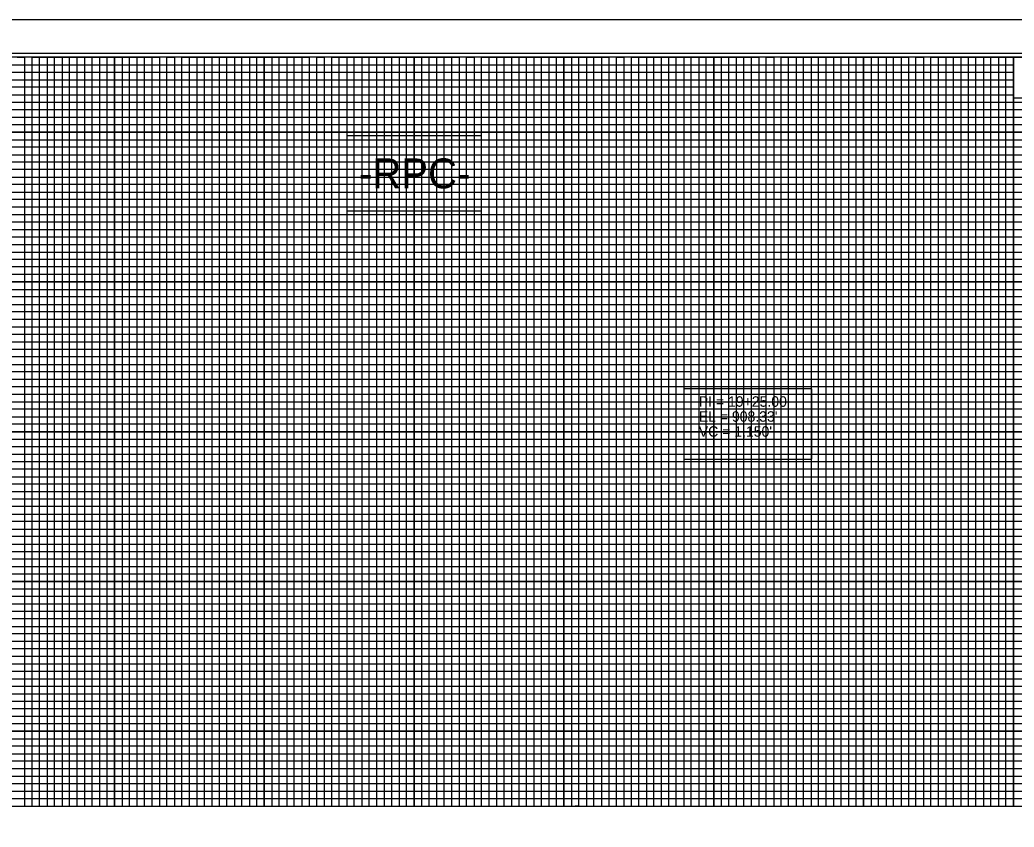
# Model space of a CAD drawing. Extents: x 1648862 to 1650855, y 808691 to 809791.
# Drawn here: x 1649516 to 1650180, y 809252 to 809791 of the extents above; entities that cross this region are included whole.
import ezdxf

# ---------------------------------------------------------------- set-up
doc = ezdxf.new("R2010")
doc.units = 0
for name, color, linetype in [('Exist Vertical Profile Horizontal Axis Label Major', 7, 'Continuous'), ('Prop Dimension Text', 7, 'Continuous'), ('Prop Grid Mask', 7, 'Continuous'), ('Prop Vertical Profile Curve Label', 7, 'Continuous'), ('Prop VPI Label', 7, 'Continuous'), ('Sheet Cutting Line CELL', 7, 'Continuous'), ('Sheet DOT Grid CELL', 7, 'Continuous'), ('Sheet Layout Profile Border Port 1', 7, 'Continuous'), ('Sheet Plot Border Inside CELL', 7, 'Continuous'), ('Sheet Plot Border Outside CELL', 7, 'Continuous'), ('Sheet Profile CELL', 7, 'Continuous'), ('Sheet Profile Grid Major CELL', 7, 'Continuous'), ('Sheet Profile Grid Middle CELL', 7, 'Continuous'), ('Sheet Profile Grid Minor CELL', 7, 'Continuous')]:
    doc.layers.add(name, color=color, linetype=linetype)

msp = doc.modelspace()

# ---------------------------------------------------------------- linework, layer by layer
at = {"layer": 'Prop Dimension Text'}
msp.add_lwpolyline([(1650179.28, 809738.96), (1650329.23, 809738.96), (1650329.23, 809766.02), (1650179.28, 809766.02)], close=True, dxfattribs=at)
at = {"layer": 'Prop Grid Mask'}
for points in [[(1649734.28, 809713.52), (1649734.28, 809663.52), (1649824.28, 809663.52), (1649824.28, 809713.52)], [(1649959.28, 809544.7), (1649959.28, 809497.7), (1650044.75, 809497.7), (1650044.75, 809544.7)]]:
    msp.add_lwpolyline(points, close=True, dxfattribs=at)
at = {"layer": 'Sheet Cutting Line CELL'}
msp.add_line((1650546.28, 809791.02), (1648862.28, 809791.02), dxfattribs=at)
at = {"layer": 'Sheet DOT Grid CELL'}
for p, q in [((1649529.28, 809266.02), (1649529.28, 809766.02)), ((1649529.28, 809266.02), (1649529.28, 809766.02)), ((1649529.28, 809266.02), (1649529.28, 809766.02)), ((1649579.28, 809266.02), (1649579.28, 809766.02)), ((1649579.28, 809266.02), (1649579.28, 809766.02)), ((1649579.28, 809266.02), (1649579.28, 809766.02)), ((1649629.28, 809266.02), (1649629.28, 809766.02)), ((1649629.28, 809266.02), (1649629.28, 809766.02)), ((1649629.28, 809266.02), (1649629.28, 809766.02)), ((1649679.28, 809266.02), (1649679.28, 809766.02)), ((1649679.28, 809266.02), (1649679.28, 809766.02)), ((1649679.28, 809266.02), (1649679.28, 809766.02)), ((1649729.28, 809266.02), (1649729.28, 809766.02)), ((1649729.28, 809266.02), (1649729.28, 809766.02)), ((1649729.28, 809266.02), (1649729.28, 809766.02)), ((1649779.28, 809266.02), (1649779.28, 809766.02)), ((1649779.28, 809266.02), (1649779.28, 809766.02)), ((1649779.28, 809266.02), (1649779.28, 809766.02)), ((1649829.28, 809266.02), (1649829.28, 809766.02)), ((1649829.28, 809266.02), (1649829.28, 809766.02)), ((1649829.28, 809266.02), (1649829.28, 809766.02)), ((1649879.28, 809266.02), (1649879.28, 809766.02)), ((1649879.28, 809266.02), (1649879.28, 809766.02)), ((1649879.28, 809266.02), (1649879.28, 809766.02)), ((1649929.28, 809266.02), (1649929.28, 809766.02)), ((1649929.28, 809266.02), (1649929.28, 809766.02)), ((1649929.28, 809266.02), (1649929.28, 809766.02)), ((1649979.28, 809266.02), (1649979.28, 809766.02)), ((1649979.28, 809266.02), (1649979.28, 809766.02)), ((1649979.28, 809266.02), (1649979.28, 809766.02)), ((1650029.28, 809266.02), (1650029.28, 809766.02)), ((1650029.28, 809266.02), (1650029.28, 809766.02)), ((1650029.28, 809266.02), (1650029.28, 809766.02)), ((1650079.28, 809266.02), (1650079.28, 809766.02)), ((1650129.28, 809266.02), (1650129.28, 809766.02)), ((1650179.28, 809266.02), (1650179.28, 809766.02)), ((1650329.23, 809716.02), (1649029.28, 809716.02)), ((1650329.23, 809716.02), (1649029.28, 809716.02)), ((1650329.23, 809716.02), (1649029.28, 809716.02)), ((1650079.28, 809266.02), (1650079.28, 809718.48)), ((1650079.28, 809266.02), (1650079.28, 809718.48)), ((1650129.28, 809266.02), (1650129.28, 809718.48)), ((1650129.28, 809266.02), (1650129.28, 809718.48)), ((1650179.28, 809266.02), (1650179.28, 809716.02)), ((1650179.28, 809266.02), (1650179.28, 809716.02)), ((1650329.23, 809666.02), (1649029.28, 809666.02)), ((1650329.23, 809666.02), (1649029.28, 809666.02)), ((1650329.23, 809666.02), (1649029.28, 809666.02)), ((1650329.28, 809616.02), (1649029.28, 809616.02)), ((1650329.28, 809616.02), (1649029.28, 809616.02)), ((1650329.28, 809616.02), (1649029.28, 809616.02)), ((1650529.28, 809566.02), (1649029.28, 809566.02)), ((1650529.28, 809566.02), (1649029.28, 809566.02)), ((1650529.28, 809566.02), (1649029.28, 809566.02)), ((1650529.28, 809516.02), (1649029.28, 809516.02)), ((1650529.28, 809516.02), (1649029.28, 809516.02)), ((1650529.28, 809516.02), (1649029.28, 809516.02)), ((1650529.28, 809466.02), (1649029.28, 809466.02)), ((1650529.28, 809466.02), (1649029.28, 809466.02)), ((1650529.28, 809466.02), (1649029.28, 809466.02)), ((1650529.28, 809416.02), (1649029.28, 809416.02)), ((1650529.28, 809416.02), (1649029.28, 809416.02)), ((1650529.28, 809416.02), (1649029.28, 809416.02)), ((1650529.28, 809366.02), (1649029.28, 809366.02)), ((1650529.28, 809366.02), (1649029.28, 809366.02)), ((1650529.28, 809366.02), (1649029.28, 809366.02)), ((1650529.28, 809316.02), (1649029.28, 809316.02)), ((1650529.28, 809316.02), (1649029.28, 809316.02)), ((1650529.28, 809316.02), (1649029.28, 809316.02))]:
    msp.add_line(p, q, dxfattribs=at)
at = {"layer": 'Sheet Layout Profile Border Port 1'}
msp.add_lwpolyline([(1649079.28, 809604.97), (1649079.28, 809266.02), (1650479.28, 809266.02), (1650479.28, 809604.97)], dxfattribs=at)
at = {"layer": 'Sheet Plot Border Inside CELL'}
msp.add_lwpolyline([(1648875.28, 808713.47), (1650541.78, 808713.47), (1650541.78, 809768.57), (1648875.28, 809768.57)], close=True, dxfattribs=at)
at = {"layer": 'Sheet Plot Border Outside CELL'}
msp.add_lwpolyline([(1648862.28, 808691.02), (1650546.28, 808691.02), (1650546.28, 809791.02), (1648862.28, 809791.02)], close=True, dxfattribs=at)
at = {"layer": 'Sheet Profile CELL'}
msp.add_line((1649029.28, 809266.02), (1650529.28, 809266.02), dxfattribs=at)
msp.add_lwpolyline([(1650529.28, 809766.02), (1649029.28, 809766.02), (1649029.28, 808716.02), (1650529.28, 808716.02)], close=True, dxfattribs=at)
at = {"layer": 'Sheet Profile Grid Major CELL'}
for points in [[(1649479.28, 809266.02), (1649529.28, 809266.02), (1649529.28, 809766.02), (1649579.28, 809766.02), (1649579.28, 809266.02), (1649629.28, 809266.02), (1649629.28, 809766.02), (1649679.28, 809766.02), (1649679.28, 809266.02), (1649729.28, 809266.02), (1649729.28, 809766.02), (1649779.28, 809766.02), (1649779.28, 809266.02), (1649829.28, 809266.02), (1649829.28, 809766.02), (1649879.28, 809766.02), (1649879.28, 809266.02), (1649929.28, 809266.02), (1649929.28, 809766.02), (1649979.28, 809766.02), (1649979.28, 809266.02), (1650029.28, 809266.02), (1650029.28, 809766.02), (1650079.28, 809766.02), (1650079.28, 809266.02), (1650129.28, 809266.02), (1650129.28, 809766.02), (1650179.28, 809766.02), (1650179.28, 809266.02), (1650229.28, 809266.02)], [(1649029.28, 809716.02), (1650329.28, 809716.02)], [(1650329.28, 809666.02), (1649029.28, 809666.02), (1649029.28, 809616.02), (1650329.28, 809616.02)], [(1650529.28, 809566.02), (1649029.28, 809566.02), (1649029.28, 809516.02), (1650529.28, 809516.02)], [(1650529.28, 809466.02), (1649029.28, 809466.02), (1649029.28, 809416.02), (1650529.28, 809416.02)], [(1650529.28, 809366.02), (1649029.28, 809366.02), (1649029.28, 809366.02), (1649029.28, 809316.02), (1650529.28, 809316.02)]]:
    msp.add_lwpolyline(points, dxfattribs=at)
at = {"layer": 'Sheet Profile Grid Middle CELL'}
msp.add_line((1649029.28, 809741.02), (1650179.28, 809741.02), dxfattribs=at)
for points in [[(1649504.28, 809266.02), (1649554.28, 809266.02), (1649554.28, 809766.02), (1649604.28, 809766.02), (1649604.28, 809266.02), (1649654.28, 809266.02), (1649654.28, 809266.02), (1649654.28, 809766.02), (1649704.28, 809766.02), (1649704.28, 809266.02), (1649754.28, 809266.02), (1649754.28, 809766.02), (1649804.28, 809766.02), (1649804.28, 809266.02), (1649854.28, 809266.02), (1649854.28, 809766.02), (1649904.28, 809766.02), (1649904.28, 809266.02), (1649954.28, 809266.02), (1649954.28, 809766.02), (1650004.28, 809766.02), (1650004.28, 809266.02), (1650054.28, 809266.02), (1650054.28, 809766.02), (1650104.28, 809766.02), (1650104.28, 809266.02), (1650154.28, 809266.02), (1650154.28, 809766.02), (1650204.28, 809766.02)], [(1650329.28, 809691.02), (1649029.28, 809691.02), (1649029.28, 809641.02), (1650329.28, 809641.02)], [(1650529.28, 809591.02), (1649029.28, 809591.02), (1649029.28, 809541.02), (1650354.28, 809541.02)], [(1650529.28, 809491.02), (1649029.28, 809491.02), (1649029.28, 809441.02), (1650529.28, 809441.02)], [(1650529.28, 809391.02), (1649029.28, 809391.02), (1649029.28, 809341.02), (1650529.28, 809341.02)], [(1650529.28, 809291.02), (1649029.28, 809291.02)]]:
    msp.add_lwpolyline(points, dxfattribs=at)
at = {"layer": 'Sheet Profile Grid Minor CELL'}
for p, q in [((1649079.28, 809761.02), (1650037.42, 809761.02)), ((1649079.28, 809761.02), (1650179.28, 809761.02)), ((1649614.28, 809766.02), (1649619.28, 809766.02)), ((1649624.28, 809766.02), (1649634.28, 809766.02)), ((1649639.28, 809766.02), (1649644.28, 809766.02)), ((1649649.28, 809766.02), (1649659.28, 809766.02)), ((1649664.28, 809766.02), (1649669.28, 809766.02)), ((1649674.28, 809766.02), (1649684.28, 809766.02)), ((1649689.28, 809766.02), (1649694.28, 809766.02)), ((1649699.28, 809766.02), (1649709.28, 809766.02)), ((1649714.28, 809766.02), (1649719.28, 809766.02)), ((1649724.28, 809766.02), (1649734.28, 809766.02)), ((1649739.28, 809766.02), (1649744.28, 809766.02)), ((1649749.28, 809766.02), (1649759.28, 809766.02)), ((1649764.28, 809766.02), (1649769.28, 809766.02)), ((1649774.28, 809766.02), (1649784.28, 809766.02)), ((1649789.28, 809766.02), (1649794.28, 809766.02)), ((1649799.28, 809766.02), (1649809.28, 809766.02)), ((1649814.28, 809766.02), (1649819.28, 809766.02)), ((1649824.28, 809766.02), (1649834.28, 809766.02)), ((1649839.28, 809766.02), (1649844.28, 809766.02)), ((1649849.28, 809766.02), (1649859.28, 809766.02)), ((1649864.28, 809766.02), (1649869.28, 809766.02)), ((1649874.28, 809766.02), (1649884.28, 809766.02)), ((1649889.28, 809766.02), (1649894.28, 809766.02)), ((1649899.28, 809766.02), (1649909.28, 809766.02)), ((1650179.28, 809755.98), (1649079.28, 809755.67)), ((1650037.42, 809755.94), (1649079.28, 809755.67)), ((1649079.28, 809751.02), (1650179.28, 809751.02)), ((1650329.23, 809631.02), (1649079.28, 809631.02)), ((1650329.28, 809626.02), (1649079.28, 809626.02)), ((1650329.28, 809621.02), (1649079.28, 809621.02)), ((1649079.28, 809611.02), (1650329.28, 809611.02)), ((1650329.28, 809606.02), (1649079.28, 809606.02)), ((1649079.28, 809601.02), (1650479.28, 809601.02)), ((1650479.28, 809581.02), (1649079.28, 809581.02)), ((1649079.28, 809576.02), (1650479.28, 809576.02)), ((1650479.28, 809556.02), (1649079.28, 809556.02)), ((1649079.28, 809551.02), (1650479.28, 809551.02)), ((1650479.28, 809531.02), (1649079.28, 809531.02)), ((1649079.28, 809526.02), (1650479.28, 809526.02)), ((1650479.28, 809521.02), (1649079.28, 809521.02)), ((1649079.28, 809511.02), (1650479.28, 809511.02)), ((1650479.28, 809506.02), (1649079.28, 809506.02)), ((1649079.28, 809501.02), (1650479.28, 809501.02)), ((1650479.28, 809496.02), (1649079.28, 809496.02)), ((1649079.28, 809486.02), (1650479.28, 809486.02)), ((1650479.28, 809481.02), (1649079.28, 809481.02)), ((1649079.28, 809476.02), (1650479.28, 809476.02)), ((1650479.28, 809471.02), (1649079.28, 809471.02)), ((1649079.28, 809461.02), (1650479.28, 809461.02)), ((1650479.28, 809456.02), (1649079.28, 809456.02)), ((1649079.28, 809451.02), (1650479.28, 809451.02)), ((1650479.28, 809446.02), (1649079.28, 809446.02)), ((1649079.28, 809436.02), (1650479.28, 809436.02)), ((1650479.28, 809431.02), (1649079.28, 809431.02)), ((1649079.28, 809426.02), (1650479.28, 809426.02)), ((1650479.28, 809421.02), (1649079.28, 809421.02)), ((1649079.28, 809411.02), (1650479.28, 809411.02)), ((1650479.28, 809406.02), (1649079.28, 809406.02)), ((1649079.28, 809401.02), (1650479.28, 809401.02)), ((1650479.28, 809396.02), (1649079.28, 809396.02)), ((1649079.28, 809386.02), (1650479.28, 809386.02)), ((1650479.28, 809381.02), (1649079.28, 809381.02)), ((1650479.28, 809376.02), (1649079.28, 809376.02)), ((1650479.28, 809371.02), (1649079.28, 809371.02)), ((1649079.28, 809361.02), (1650479.28, 809361.02)), ((1650479.28, 809356.02), (1649079.28, 809356.02)), ((1649079.28, 809351.02), (1650479.28, 809351.02)), ((1650479.28, 809346.02), (1649079.28, 809346.02)), ((1649079.28, 809336.02), (1650479.28, 809336.02)), ((1650479.28, 809331.02), (1649079.28, 809331.02)), ((1649079.28, 809326.02), (1650479.28, 809326.02)), ((1650479.28, 809321.02), (1649079.28, 809321.02)), ((1649079.28, 809311.02), (1650479.28, 809311.02)), ((1650479.28, 809306.02), (1649079.28, 809306.02)), ((1649079.28, 809301.02), (1650479.28, 809301.02)), ((1650479.28, 809296.02), (1649079.28, 809296.02)), ((1649079.28, 809286.02), (1650479.28, 809286.02)), ((1650479.28, 809281.02), (1649079.28, 809281.02)), ((1649079.28, 809276.02), (1650479.28, 809276.02)), ((1649609.28, 809266.02), (1649614.28, 809266.02)), ((1649619.28, 809266.02), (1649624.28, 809266.02)), ((1649634.28, 809266.02), (1649639.28, 809266.02)), ((1649644.28, 809266.02), (1649649.28, 809266.02)), ((1649659.28, 809266.02), (1649664.28, 809266.02)), ((1649669.28, 809266.02), (1649674.28, 809266.02)), ((1649684.28, 809266.02), (1649689.28, 809266.02)), ((1649694.28, 809266.02), (1649699.28, 809266.02)), ((1649709.28, 809266.02), (1649714.28, 809266.02)), ((1649719.28, 809266.02), (1649724.28, 809266.02)), ((1649734.28, 809266.02), (1649734.28, 809266.02)), ((1649734.28, 809266.02), (1649739.28, 809266.02)), ((1649744.28, 809266.02), (1649749.28, 809266.02)), ((1649759.28, 809266.02), (1649764.28, 809266.02)), ((1649769.28, 809266.02), (1649774.28, 809266.02)), ((1649784.28, 809266.02), (1649789.28, 809266.02)), ((1649794.28, 809266.02), (1649799.28, 809266.02)), ((1649809.28, 809266.02), (1649814.28, 809266.02)), ((1649819.28, 809266.02), (1649824.28, 809266.02)), ((1649834.28, 809266.02), (1649839.28, 809266.02)), ((1649844.28, 809266.02), (1649849.28, 809266.02)), ((1649859.28, 809266.02), (1649864.28, 809266.02)), ((1649869.28, 809266.02), (1649874.28, 809266.02)), ((1649884.28, 809266.02), (1649888.98, 809266.57)), ((1649888.98, 809266.57), (1649889.28, 809266.02)), ((1649894.28, 809266.02), (1649899.28, 809266.02)), ((1649909.28, 809266.02), (1649914.28, 809266.02)), ((1650159.28, 809266.02), (1650164.28, 809266.02))]:
    msp.add_line(p, q, dxfattribs=at)
for points in [[(1649514.28, 809766.02), (1649519.28, 809766.02), (1649519.28, 809266.02), (1649524.28, 809266.02), (1649524.28, 809766.02), (1649534.28, 809766.02), (1649534.28, 809266.02), (1649539.28, 809266.02), (1649539.28, 809766.02), (1649544.28, 809766.02), (1649544.28, 809266.02), (1649549.28, 809266.02), (1649549.28, 809766.02), (1649559.28, 809766.02), (1649559.28, 809266.02), (1649564.28, 809266.02), (1649564.28, 809766.02), (1649569.28, 809766.02), (1649569.28, 809266.02), (1649574.28, 809266.02), (1649574.28, 809766.02), (1649584.28, 809766.02), (1649584.28, 809266.02), (1649589.28, 809266.02), (1649589.28, 809766.02), (1649594.28, 809766.02), (1649594.28, 809266.02), (1649599.28, 809266.02), (1649599.28, 809766.02), (1649609.28, 809766.02)], [(1649609.28, 809766.02), (1649609.28, 809266.02), (1649614.28, 809266.02), (1649614.28, 809766.02), (1649619.28, 809766.02), (1649619.28, 809266.02), (1649624.28, 809266.02), (1649624.28, 809766.02), (1649634.28, 809766.02), (1649634.28, 809266.02), (1649639.28, 809266.02), (1649639.28, 809766.02), (1649644.28, 809766.02), (1649644.28, 809266.02), (1649649.28, 809266.02), (1649649.28, 809766.02), (1649659.28, 809766.02), (1649659.28, 809266.02), (1649664.28, 809266.02), (1649664.28, 809766.02), (1649669.28, 809766.02), (1649669.28, 809266.02), (1649674.28, 809266.02), (1649674.28, 809766.02), (1649684.28, 809766.02), (1649684.28, 809266.02), (1649689.28, 809266.02), (1649689.28, 809766.02), (1649694.28, 809766.02), (1649694.28, 809266.02), (1649699.28, 809266.02), (1649699.28, 809766.02), (1649709.28, 809766.02), (1649709.28, 809266.02), (1649714.28, 809266.02), (1649714.28, 809766.02), (1649719.28, 809766.02), (1649719.28, 809266.02), (1649724.28, 809266.02), (1649724.28, 809766.02), (1649734.28, 809766.02), (1649734.28, 809266.02), (1649734.28, 809266.02), (1649739.28, 809266.02), (1649739.28, 809766.02), (1649744.28, 809766.02), (1649744.28, 809266.02), (1649749.28, 809266.02), (1649749.28, 809766.02), (1649759.28, 809766.02), (1649759.28, 809266.02), (1649764.28, 809266.02), (1649764.28, 809766.02), (1649769.28, 809766.02), (1649769.28, 809266.02), (1649774.28, 809266.02), (1649774.28, 809766.02), (1649784.28, 809766.02), (1649784.28, 809266.02), (1649789.28, 809266.02), (1649789.28, 809766.02), (1649794.28, 809766.02), (1649794.28, 809266.02), (1649799.28, 809266.02), (1649799.28, 809766.02), (1649809.28, 809766.02), (1649809.28, 809266.02), (1649814.28, 809266.02), (1649814.28, 809766.02), (1649819.28, 809766.02), (1649819.28, 809266.02), (1649824.28, 809266.02), (1649824.28, 809766.02), (1649834.28, 809766.02), (1649834.28, 809266.02), (1649839.28, 809266.02), (1649839.28, 809766.02), (1649844.28, 809766.02), (1649844.28, 809266.02), (1649849.28, 809266.02), (1649849.28, 809766.02), (1649859.28, 809766.02), (1649859.28, 809266.02), (1649864.28, 809266.02), (1649864.28, 809766.02), (1649869.28, 809766.02), (1649869.28, 809266.02), (1649874.28, 809266.02), (1649874.28, 809766.02), (1649884.28, 809766.02), (1649884.28, 809266.02), (1649888.98, 809266.57), (1649889.28, 809266.02), (1649889.28, 809766.02), (1649894.28, 809766.02), (1649894.28, 809266.02), (1649899.28, 809266.02), (1649899.28, 809766.02), (1649909.28, 809766.02), (1649909.28, 809266.02), (1649914.28, 809266.02)], [(1649914.28, 809266.02), (1649914.28, 809766.02), (1649919.28, 809766.02), (1649919.28, 809266.02), (1649924.28, 809266.02), (1649924.28, 809766.02), (1649934.28, 809766.02), (1649934.28, 809266.02), (1649939.28, 809266.02), (1649939.28, 809766.02), (1649944.28, 809766.02), (1649944.28, 809266.02), (1649949.28, 809266.02), (1649949.28, 809766.02), (1649959.28, 809766.02), (1649959.28, 809266.02), (1649964.28, 809266.02), (1649964.28, 809766.02), (1649969.28, 809766.02), (1649969.28, 809266.02), (1649974.28, 809266.02), (1649974.28, 809766.02), (1649984.28, 809766.02), (1649984.28, 809266.02), (1649989.28, 809266.02), (1649989.28, 809766.02), (1649994.28, 809766.02), (1649994.28, 809266.02), (1649999.28, 809266.02), (1649999.28, 809766.02), (1650009.28, 809766.02), (1650009.28, 809266.02), (1650014.28, 809266.02), (1650014.28, 809766.02), (1650019.28, 809766.02), (1650019.28, 809266.02), (1650024.28, 809266.02), (1650024.28, 809766.02), (1650034.28, 809766.02), (1650034.28, 809266.02), (1650039.28, 809266.02), (1650039.28, 809766.02), (1650044.28, 809766.02), (1650044.28, 809266.02), (1650049.28, 809266.02), (1650049.28, 809766.02), (1650059.28, 809766.02), (1650059.28, 809266.02), (1650064.28, 809266.02), (1650064.28, 809766.02), (1650069.28, 809766.02), (1650069.28, 809266.02), (1650074.28, 809266.02), (1650074.28, 809766.02), (1650084.28, 809766.02), (1650084.28, 809266.02), (1650089.28, 809266.02), (1650089.28, 809766.02), (1650094.28, 809766.02), (1650094.28, 809266.02), (1650099.28, 809266.02), (1650099.28, 809766.02), (1650109.28, 809766.02), (1650109.28, 809266.02), (1650114.28, 809266.02), (1650114.28, 809766.02), (1650119.28, 809766.02), (1650119.28, 809266.02), (1650124.28, 809266.02), (1650124.28, 809766.02), (1650134.28, 809766.02), (1650134.28, 809266.02), (1650139.28, 809266.02), (1650139.28, 809766.02), (1650144.28, 809766.02), (1650144.28, 809266.02), (1650149.28, 809266.02), (1650149.28, 809766.02), (1650159.28, 809766.02), (1650159.28, 809266.02), (1650164.28, 809266.02), (1650164.28, 809766.02), (1650169.28, 809766.02), (1650169.28, 809266.02), (1650174.28, 809266.02), (1650174.28, 809766.02), (1650184.28, 809766.02)], [(1650179.28, 809746.02), (1649079.28, 809746.02), (1649079.28, 809736.02), (1650329.28, 809736.02)], [(1650329.23, 809731.02), (1649079.28, 809731.02), (1649079.28, 809726.02), (1650329.28, 809726.02)], [(1650329.28, 809721.02), (1649079.28, 809721.02), (1649079.28, 809711.02), (1650329.28, 809711.02)], [(1650329.28, 809706.02), (1649079.28, 809706.02), (1649079.28, 809701.02), (1650329.28, 809701.02)], [(1650329.28, 809696.02), (1649079.28, 809696.02), (1649079.28, 809686.02), (1650329.28, 809686.02)], [(1650329.28, 809681.02), (1649079.28, 809681.02), (1649079.28, 809676.02), (1650329.28, 809676.02)], [(1650329.28, 809671.02), (1649079.28, 809671.02), (1649079.28, 809661.02), (1650329.28, 809661.02)], [(1650329.28, 809655.92), (1649079.38, 809655.92), (1649079.38, 809651.02), (1650329.28, 809651.02)], [(1650329.28, 809646.02), (1649079.28, 809646.02), (1649079.28, 809636.02), (1650329.28, 809636.02)], [(1650479.28, 809596.02), (1649079.28, 809596.02), (1649079.28, 809586.02), (1650479.28, 809586.02)], [(1650479.28, 809571.02), (1649079.28, 809571.02), (1649079.28, 809561.02), (1650479.28, 809561.02)], [(1650479.28, 809546.02), (1649079.28, 809546.02), (1649079.28, 809536.02), (1650479.28, 809536.02)], [(1650479.28, 809271.02), (1649079.28, 809271.02)]]:
    msp.add_lwpolyline(points, dxfattribs=at)

# ---------------------------------------------------------------- texts
at = {"layer": 'Exist Vertical Profile Horizontal Axis Label Major'}
msp.add_text('-RPC-', height=20, dxfattribs=at).set_placement((1649742.49, 809678.52))
at = {"layer": 'Prop Vertical Profile Curve Label'}
msp.add_text("VC = 1,150'", height=7, dxfattribs=at).set_placement((1649969.28, 809512.7))
at = {"layer": 'Prop VPI Label'}
for s, p in [('PI = 19+25.00', (1649969.28, 809532.7)), ("EL = 908.33'", (1649969.28, 809522.7))]:
    msp.add_text(s, height=7, dxfattribs=at).set_placement(p)

doc.saveas('drawing.dxf')
